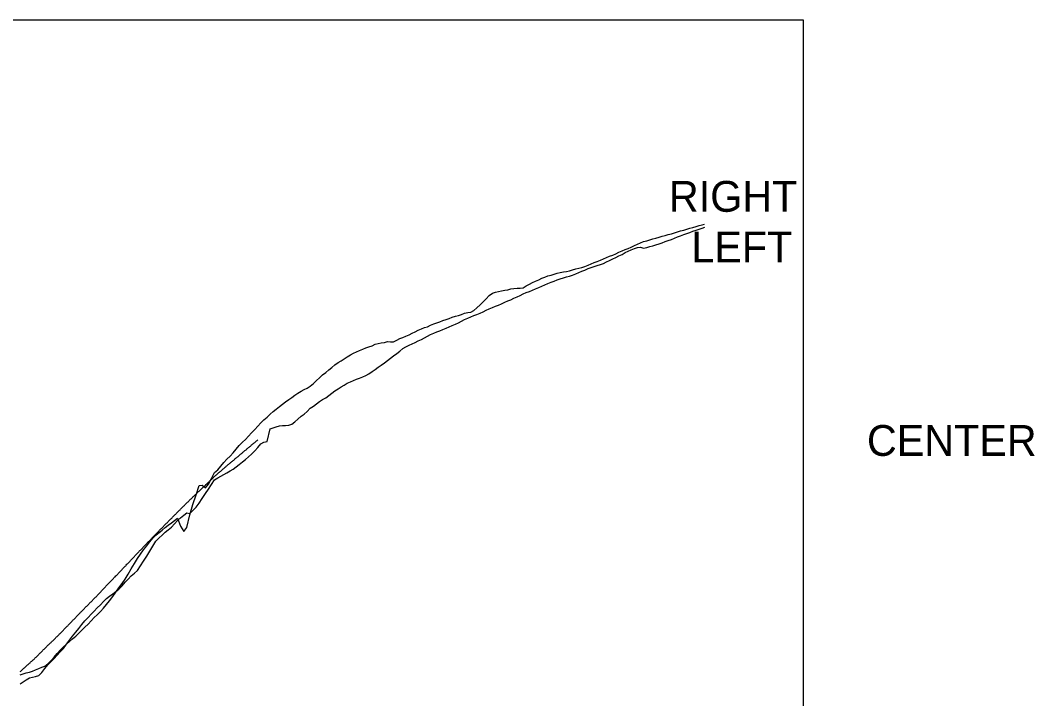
# Model space of a CAD drawing. Extents: x 1733584 to 1737559, y 1214897 to 1219897.
# Drawn here: x 1735916 to 1737559, y 1218220 to 1219320 of the extents above; entities that cross this region are included whole.
import ezdxf

# ---------------------------------------------------------------- set-up
doc = ezdxf.new("R2010")
doc.units = 0
for name, color, linetype in [('RD_DDB_Profile_EX', 7, 'Continuous'), ('RD_Sketch1', 7, 'Continuous'), ('RD_Sketch2', 7, 'Continuous'), ('RD_Sketch8', 7, 'Continuous')]:
    doc.layers.add(name, color=color, linetype=linetype)

msp = doc.modelspace()

# ---------------------------------------------------------------- linework, layer by layer
at = {"layer": 'RD_DDB_Profile_EX'}
for points in [[(1736280.3, 1218623.3), (1736281.3, 1218624.1), (1736282.3, 1218625), (1736283.3, 1218625.8), (1736284.3, 1218626.7), (1736285.3, 1218627.5), (1736286.3, 1218628.3), (1736287.3, 1218629.1), (1736288.3, 1218630), (1736289.3, 1218630.8), (1736290.3, 1218631.7), (1736291.3, 1218632.5), (1736292.3, 1218633.3), (1736293.3, 1218634.2), (1736294.3, 1218635), (1736295.3, 1218635.8), (1736296.3, 1218636.7), (1736297.3, 1218637.5), (1736298.3, 1218638.3), (1736299.3, 1218639.2), (1736300.3, 1218640), (1736300.4, 1218640)], [(1736180.3, 1218532.8), (1736181.3, 1218533.8), (1736182.3, 1218534.8), (1736183.3, 1218535.8), (1736184.3, 1218536.8), (1736185.3, 1218537.8), (1736186.3, 1218538.8), (1736187.3, 1218539.7), (1736188.3, 1218540.7), (1736189.3, 1218541.7), (1736190.3, 1218542.6), (1736191.3, 1218543.6), (1736192.3, 1218544.5), (1736193.3, 1218545.5), (1736194.3, 1218546.5), (1736195.3, 1218547.4), (1736196.3, 1218548.4), (1736197.3, 1218549.4), (1736198.3, 1218550.3), (1736199.3, 1218551.3), (1736200.3, 1218552.2), (1736201.3, 1218553.2), (1736202.3, 1218554.1), (1736203.3, 1218555.1), (1736204.3, 1218556.1), (1736205.3, 1218557), (1736206.3, 1218558), (1736207.3, 1218558.9), (1736208.3, 1218559.9), (1736209.3, 1218560.8), (1736210.3, 1218561.8), (1736211.3, 1218562.7), (1736212.3, 1218563.7), (1736213.3, 1218564.6), (1736214.3, 1218565.6), (1736215.3, 1218566.5), (1736216.3, 1218567.5), (1736217.3, 1218568.4), (1736218.3, 1218569.4), (1736219.3, 1218570.3), (1736220.3, 1218571.3), (1736221.3, 1218572.2), (1736222.3, 1218573.2), (1736223.3, 1218574.1), (1736224.3, 1218575), (1736225.3, 1218576), (1736226.3, 1218576.9), (1736227.3, 1218577.9), (1736228.3, 1218578.8), (1736229.3, 1218579.8), (1736230.3, 1218580.7), (1736231.3, 1218581.6), (1736232.3, 1218582.6), (1736233.3, 1218583.5), (1736234.3, 1218584.4), (1736235.3, 1218585.3), (1736236.3, 1218586.1), (1736237.3, 1218587), (1736238.3, 1218587.8), (1736239.3, 1218588.7), (1736240.3, 1218589.5), (1736241.3, 1218590.4), (1736242.3, 1218591.3), (1736243.3, 1218592.1), (1736244.3, 1218593), (1736245.3, 1218593.8), (1736246.3, 1218594.7), (1736247.3, 1218595.5), (1736248.3, 1218596.4), (1736249.3, 1218597.2), (1736250.3, 1218598.1), (1736251.3, 1218598.9), (1736252.3, 1218599.8), (1736253.3, 1218600.6), (1736254.3, 1218601.5), (1736255.3, 1218602.3), (1736256.3, 1218603.2), (1736257.3, 1218604), (1736258.3, 1218604.9), (1736259.3, 1218605.7), (1736260.3, 1218606.5), (1736261.3, 1218607.3), (1736262.3, 1218608.2), (1736263.3, 1218609), (1736264.3, 1218609.9), (1736265.3, 1218610.7), (1736266.3, 1218611.6), (1736267.3, 1218612.4), (1736268.3, 1218613.2), (1736269.3, 1218614.1), (1736270.3, 1218614.9), (1736271.3, 1218615.8), (1736272.3, 1218616.6), (1736273.3, 1218617.4), (1736274.3, 1218618.3), (1736275.3, 1218619.1), (1736276.3, 1218620), (1736277.3, 1218620.8), (1736278.3, 1218621.6), (1736279.3, 1218622.5), (1736280.3, 1218623.3)], [(1736080.3, 1218429.8), (1736081.3, 1218430.8), (1736082.3, 1218431.9), (1736083.3, 1218432.9), (1736084.3, 1218433.9), (1736085.3, 1218435), (1736086.3, 1218436), (1736087.3, 1218437.1), (1736088.3, 1218438.2), (1736089.3, 1218439.2), (1736090.3, 1218440.3), (1736091.3, 1218441.3), (1736092.3, 1218442.4), (1736093.3, 1218443.5), (1736094.3, 1218444.5), (1736095.3, 1218445.6), (1736096.3, 1218446.6), (1736097.3, 1218447.7), (1736098.3, 1218448.7), (1736099.3, 1218449.8), (1736100.3, 1218450.8), (1736101.3, 1218451.9), (1736102.3, 1218452.9), (1736103.3, 1218454), (1736104.3, 1218455), (1736105.3, 1218456.1), (1736106.3, 1218457.2), (1736107.3, 1218458.2), (1736108.3, 1218459.3), (1736109.3, 1218460.4), (1736110.3, 1218461.4), (1736111.3, 1218462.5), (1736112.3, 1218463.5), (1736113.3, 1218464.6), (1736114.3, 1218465.6), (1736115.3, 1218466.7), (1736116.3, 1218467.7), (1736117.3, 1218468.7), (1736118.3, 1218469.8), (1736119.3, 1218470.8), (1736120.3, 1218471.9), (1736121.3, 1218472.9), (1736122.3, 1218473.9), (1736123.3, 1218475), (1736124.3, 1218476), (1736125.3, 1218477), (1736126.3, 1218478.1), (1736127.3, 1218479.1), (1736128.3, 1218480.1), (1736129.3, 1218481.2), (1736130.3, 1218482.2), (1736131.3, 1218483.2), (1736132.3, 1218484.3), (1736133.3, 1218485.3), (1736134.3, 1218486.4), (1736135.3, 1218487.3), (1736136.3, 1218488.3), (1736137.3, 1218489.4), (1736138.3, 1218490.4), (1736139.3, 1218491.4), (1736140.3, 1218492.5), (1736141.3, 1218493.5), (1736142.3, 1218494.5), (1736143.3, 1218495.5), (1736144.3, 1218496.5), (1736145.3, 1218497.6), (1736146.3, 1218498.6), (1736147.3, 1218499.6), (1736148.3, 1218500.6), (1736149.3, 1218501.6), (1736150.3, 1218502.7), (1736151.3, 1218503.7), (1736152.3, 1218504.7), (1736153.3, 1218505.7), (1736154.3, 1218506.7), (1736155.3, 1218507.7), (1736156.3, 1218508.8), (1736157.3, 1218509.8), (1736158.3, 1218510.8), (1736159.3, 1218511.8), (1736160.3, 1218512.7), (1736161.3, 1218513.7), (1736162.3, 1218514.7), (1736163.3, 1218515.7), (1736164.3, 1218516.7), (1736165.3, 1218517.8), (1736166.3, 1218518.8), (1736167.3, 1218519.8), (1736168.3, 1218520.8), (1736169.3, 1218521.8), (1736170.3, 1218522.8), (1736171.3, 1218523.8), (1736172.3, 1218524.8), (1736173.3, 1218525.8), (1736174.3, 1218526.8), (1736175.3, 1218527.8), (1736176.3, 1218528.8), (1736177.3, 1218529.8), (1736178.3, 1218530.8), (1736179.3, 1218531.8), (1736180.3, 1218532.8)], [(1735980.3, 1218326.3), (1735981.3, 1218327.2), (1735982.3, 1218328.2), (1735983.3, 1218329.2), (1735984.3, 1218330.3), (1735985.3, 1218331.4), (1735986.3, 1218332.4), (1735987.3, 1218333.5), (1735988.3, 1218334.5), (1735989.3, 1218335.6), (1735990.3, 1218336.7), (1735991.3, 1218337.7), (1735992.3, 1218338.7), (1735993.3, 1218339.8), (1735994.3, 1218340.8), (1735995.3, 1218341.8), (1735996.3, 1218342.9), (1735997.3, 1218343.9), (1735998.3, 1218344.9), (1735999.3, 1218345.9), (1736000.3, 1218347), (1736001.3, 1218348), (1736002.3, 1218349), (1736003.3, 1218350), (1736004.3, 1218351.1), (1736005.3, 1218352.1), (1736006.3, 1218353.1), (1736007.3, 1218354.1), (1736008.3, 1218355.2), (1736009.3, 1218356.2), (1736010.3, 1218357.3), (1736011.3, 1218358.3), (1736012.3, 1218359.3), (1736013.3, 1218360.4), (1736014.3, 1218361.4), (1736015.3, 1218362.5), (1736016.3, 1218363.5), (1736017.3, 1218364.5), (1736018.3, 1218365.5), (1736019.3, 1218366.5), (1736020.3, 1218367.5), (1736021.3, 1218368.5), (1736022.3, 1218369.6), (1736023.3, 1218370.6), (1736024.3, 1218371.6), (1736025.3, 1218372.6), (1736026.3, 1218373.6), (1736027.3, 1218374.6), (1736028.3, 1218375.6), (1736029.3, 1218376.6), (1736030.3, 1218377.6), (1736031.3, 1218378.6), (1736032.3, 1218379.6), (1736033.3, 1218380.6), (1736034.3, 1218381.6), (1736035.3, 1218382.6), (1736036.3, 1218383.7), (1736037.3, 1218384.7), (1736038.3, 1218385.7), (1736039.3, 1218386.7), (1736040.3, 1218387.8), (1736041.3, 1218388.8), (1736042.3, 1218389.9), (1736043.3, 1218391), (1736044.3, 1218392), (1736045.3, 1218393.1), (1736046.3, 1218394.2), (1736047.3, 1218395.2), (1736048.3, 1218396.3), (1736049.3, 1218397.4), (1736050.3, 1218398.4), (1736051.3, 1218399.5), (1736052.3, 1218400.5), (1736053.3, 1218401.6), (1736054.3, 1218402.7), (1736055.3, 1218403.7), (1736056.3, 1218404.8), (1736057.3, 1218405.8), (1736058.3, 1218406.9), (1736059.3, 1218408), (1736060.3, 1218409), (1736061.3, 1218410), (1736062.3, 1218411), (1736063.3, 1218412), (1736064.3, 1218413), (1736065.3, 1218414), (1736066.3, 1218415.1), (1736067.3, 1218416.1), (1736068.3, 1218417.2), (1736069.3, 1218418.2), (1736070.3, 1218419.3), (1736071.3, 1218420.3), (1736072.3, 1218421.4), (1736073.3, 1218422.4), (1736074.3, 1218423.5), (1736075.3, 1218424.5), (1736076.3, 1218425.6), (1736077.3, 1218426.6), (1736078.3, 1218427.7), (1736079.3, 1218428.7), (1736080.3, 1218429.8)], [(1735915.3, 1218264.2), (1735916.3, 1218265.1), (1735917.3, 1218266), (1735918.3, 1218266.9), (1735919.3, 1218267.8), (1735920.3, 1218268.7), (1735921.3, 1218269.6), (1735922.3, 1218270.5), (1735923.3, 1218271.4), (1735924.3, 1218272.3), (1735925.3, 1218273.2), (1735926.3, 1218274.1), (1735927.3, 1218275), (1735928.3, 1218275.9), (1735929.3, 1218276.8), (1735930.3, 1218277.7), (1735931.3, 1218278.6), (1735932.3, 1218279.5), (1735933.3, 1218280.4), (1735934.3, 1218281.3), (1735935.3, 1218282.2), (1735936.3, 1218283.1), (1735937.3, 1218284.1), (1735938.3, 1218285), (1735939.3, 1218286), (1735940.3, 1218287), (1735941.3, 1218287.9), (1735942.3, 1218288.9), (1735943.3, 1218289.9), (1735944.3, 1218290.9), (1735945.3, 1218291.9), (1735946.3, 1218292.9), (1735947.3, 1218293.9), (1735948.3, 1218294.9), (1735949.3, 1218295.9), (1735950.3, 1218296.9), (1735951.3, 1218297.9), (1735952.3, 1218298.9), (1735953.3, 1218299.9), (1735954.3, 1218300.9), (1735955.3, 1218301.9), (1735956.3, 1218302.9), (1735957.3, 1218303.9), (1735958.3, 1218304.9), (1735959.3, 1218305.9), (1735960.3, 1218306.9), (1735961.3, 1218307.9), (1735962.3, 1218308.8), (1735963.3, 1218309.7), (1735964.3, 1218310.7), (1735965.3, 1218311.6), (1735966.3, 1218312.5), (1735967.3, 1218313.5), (1735968.3, 1218314.4), (1735969.3, 1218315.4), (1735970.3, 1218316.4), (1735971.3, 1218317.4), (1735972.3, 1218318.4), (1735973.3, 1218319.4), (1735974.3, 1218320.4), (1735975.3, 1218321.3), (1735976.3, 1218322.3), (1735977.3, 1218323.3), (1735978.3, 1218324.3), (1735979.3, 1218325.3), (1735980.3, 1218326.3)]]:
    msp.add_lwpolyline(points, dxfattribs=at)
at = {"layer": 'RD_Sketch1'}
for points in [[(1736880.3, 1218935.8), (1736885.3, 1218938.2), (1736890.3, 1218940.6), (1736895.3, 1218943.9), (1736900.3, 1218946.2), (1736905.3, 1218948.1), (1736910.3, 1218950.1), (1736915.3, 1218951.8), (1736920.3, 1218952.2), (1736925.3, 1218950.6), (1736930.3, 1218951.7), (1736935.3, 1218953.3), (1736940.3, 1218954.8), (1736945.3, 1218956.3), (1736950.3, 1218958), (1736955.3, 1218959.7), (1736960.3, 1218961.4), (1736965.3, 1218963.1), (1736970.3, 1218965), (1736975.3, 1218967), (1736980.3, 1218969), (1736985.3, 1218970.9), (1736990.3, 1218972.9), (1736995.3, 1218974.7), (1737000.3, 1218976.4), (1737005.3, 1218978.1), (1737010.3, 1218979.8), (1737015.3, 1218981.5), (1737020.3, 1218983.3), (1737024.6, 1218984.8)], [(1736380.3, 1218686.2), (1736385.3, 1218691.2), (1736390.3, 1218694.9), (1736395.3, 1218698.5), (1736400.3, 1218702.1), (1736405.3, 1218705.4), (1736410.3, 1218708.2), (1736415.3, 1218711.8), (1736420.3, 1218715.6), (1736425.3, 1218719.4), (1736430.3, 1218722.9), (1736435.3, 1218725.9), (1736440.3, 1218728.9), (1736445.3, 1218731.7), (1736450.3, 1218734.2), (1736455.3, 1218736.2), (1736460.3, 1218738.2), (1736465.3, 1218740.2), (1736470.3, 1218742.3), (1736475.3, 1218744.4), (1736480.3, 1218747.3), (1736485.3, 1218750.6), (1736490.3, 1218754), (1736495.3, 1218757.7), (1736500.3, 1218761.3), (1736505.3, 1218764.9), (1736510.3, 1218768.5), (1736515.3, 1218772.3), (1736520.3, 1218776.2), (1736525.3, 1218780.2), (1736530.3, 1218784), (1736535.3, 1218787.9), (1736540.3, 1218791), (1736545.3, 1218793.3), (1736550.3, 1218795.6), (1736555.3, 1218798), (1736560.3, 1218800.4), (1736565.3, 1218802.9), (1736570.3, 1218805.4), (1736575.3, 1218808), (1736580.3, 1218810.7), (1736585.3, 1218813.1), (1736590.3, 1218814.9), (1736595.3, 1218816.8), (1736600.3, 1218818.8), (1736605.3, 1218821), (1736610.3, 1218823.4), (1736615.3, 1218825.5), (1736620.3, 1218827.6), (1736625.3, 1218829.8), (1736630.3, 1218832.4), (1736635.3, 1218835.1), (1736640.3, 1218837.2), (1736645.3, 1218839.3), (1736650.3, 1218841.6), (1736655.3, 1218843.4), (1736660.3, 1218845.2), (1736665.3, 1218847.7), (1736670.3, 1218850.1), (1736675.3, 1218852.6), (1736680.3, 1218854.6), (1736685.3, 1218856.5), (1736690.3, 1218858.6), (1736695.3, 1218860.8), (1736700.3, 1218863), (1736705.3, 1218865.2), (1736710.3, 1218867.2), (1736715.3, 1218869.5), (1736720.3, 1218871.8), (1736725.3, 1218874.3), (1736730.3, 1218876.7), (1736735.3, 1218878.7), (1736740.3, 1218880.8), (1736745.3, 1218882.9), (1736750.3, 1218884.9), (1736755.3, 1218886.9), (1736760.3, 1218889), (1736765.3, 1218891.2), (1736770.3, 1218893.4), (1736775.3, 1218895.5), (1736780.3, 1218897.4), (1736785.3, 1218899.3), (1736790.3, 1218901.3), (1736795.3, 1218902.9), (1736800.3, 1218904.1), (1736805.3, 1218905.3), (1736810.3, 1218906.9), (1736815.3, 1218909.1), (1736820.3, 1218911.3), (1736825.3, 1218913.4), (1736830.3, 1218915.2), (1736835.3, 1218917.7), (1736840.3, 1218919.5), (1736845.3, 1218921.2), (1736850.3, 1218922.9), (1736855.3, 1218924.3), (1736860.3, 1218925.8), (1736865.3, 1218928.5), (1736870.3, 1218931), (1736875.3, 1218933.4), (1736880.3, 1218935.8)], [(1735915.3, 1218244.3), (1735920.3, 1218247.5), (1735925.3, 1218250.8), (1735930.3, 1218254.2), (1735935.3, 1218255.3), (1735940.3, 1218256.2), (1735945.3, 1218257.7), (1735950.3, 1218263), (1735955.3, 1218269.3), (1735960.3, 1218275.5), (1735965.3, 1218280.6), (1735970.3, 1218285.5), (1735975.3, 1218291), (1735980.3, 1218296.4), (1735985.3, 1218302), (1735990.3, 1218308.7), (1735995.3, 1218315.4), (1736000.3, 1218321.9), (1736005.3, 1218328.3), (1736010.3, 1218334.1), (1736015.3, 1218340.8), (1736020.3, 1218346.6), (1736025.3, 1218351.9), (1736030.3, 1218357.2), (1736035.3, 1218362.5), (1736040.3, 1218367.7), (1736045.3, 1218372.8), (1736050.3, 1218377.8), (1736055.3, 1218382.8), (1736060.3, 1218386.7), (1736065.3, 1218390.5), (1736070.3, 1218394.2), (1736075.3, 1218397.8), (1736080.3, 1218403.4), (1736085.3, 1218409.1), (1736090.3, 1218414.3), (1736095.3, 1218419.4), (1736100.3, 1218423.7), (1736105.3, 1218428.3), (1736110.3, 1218435.7), (1736115.3, 1218443.4), (1736120.3, 1218451.6), (1736125.3, 1218459.6), (1736130.3, 1218467.8), (1736135.3, 1218476), (1736140.3, 1218481), (1736145.3, 1218485.7), (1736150.3, 1218490.1), (1736155.3, 1218494.3), (1736160.3, 1218498.6), (1736165.3, 1218503.7), (1736170.3, 1218509), (1736175.3, 1218513.4), (1736180.3, 1218517.8), (1736185.3, 1218521.8), (1736190.3, 1218520.6), (1736195.3, 1218525.6), (1736200.3, 1218530.9), (1736205.3, 1218537.4), (1736210.3, 1218545), (1736215.3, 1218553), (1736220.3, 1218559.9), (1736225.3, 1218567.5), (1736230.3, 1218575.4), (1736235.3, 1218578.6), (1736240.3, 1218581.1), (1736245.3, 1218583.8), (1736250.3, 1218586.7), (1736255.3, 1218589.6), (1736260.3, 1218592.7), (1736265.3, 1218596.4), (1736270.3, 1218600.2), (1736275.3, 1218604.2), (1736280.3, 1218608.2), (1736285.3, 1218612.4), (1736290.3, 1218616.9), (1736295.3, 1218622.2), (1736300.3, 1218627.8), (1736305.3, 1218633.6), (1736310.3, 1218636.4), (1736315.3, 1218637.6), (1736320.3, 1218657.7), (1736325.3, 1218659.3), (1736330.3, 1218660.9), (1736335.3, 1218662.6), (1736340.3, 1218663.4), (1736345.3, 1218663.1), (1736350.3, 1218664.1), (1736355.3, 1218665.2), (1736360.3, 1218669.1), (1736365.3, 1218673.8), (1736370.3, 1218678.4), (1736375.3, 1218681.5), (1736380.3, 1218686.2)]]:
    msp.add_lwpolyline(points, dxfattribs=at)
at = {"layer": 'RD_Sketch2'}
for points in [[(1736880.3, 1218941.8), (1736885.3, 1218944.1), (1736890.3, 1218946.4), (1736895.3, 1218948.4), (1736900.3, 1218950.4), (1736905.3, 1218952.6), (1736910.3, 1218955), (1736915.3, 1218957.3), (1736920.3, 1218959.5), (1736925.3, 1218961.5), (1736930.3, 1218962.9), (1736935.3, 1218964.3), (1736940.3, 1218965.7), (1736945.3, 1218967.2), (1736950.3, 1218968.6), (1736955.3, 1218970), (1736960.3, 1218971.4), (1736965.3, 1218972.9), (1736970.3, 1218974.3), (1736975.3, 1218975.8), (1736980.3, 1218977.2), (1736985.3, 1218978.7), (1736990.3, 1218980.1), (1736995.3, 1218981.6), (1737000.3, 1218983.1), (1737005.3, 1218984.5), (1737010.3, 1218986), (1737015.3, 1218987.5), (1737020.3, 1218988.9), (1737023.7, 1218989.9)], [(1736380.3, 1218724), (1736385.3, 1218727.1), (1736390.3, 1218731.2), (1736395.3, 1218736), (1736400.3, 1218740.7), (1736405.3, 1218745.2), (1736410.3, 1218749.3), (1736415.3, 1218753.4), (1736420.3, 1218757.5), (1736425.3, 1218761.4), (1736430.3, 1218765.2), (1736435.3, 1218768.4), (1736440.3, 1218771.6), (1736445.3, 1218774.7), (1736450.3, 1218777.6), (1736455.3, 1218780.3), (1736460.3, 1218782.8), (1736465.3, 1218785.1), (1736470.3, 1218787.2), (1736475.3, 1218789.1), (1736480.3, 1218790.9), (1736485.3, 1218792.4), (1736490.3, 1218795.4), (1736495.3, 1218796.4), (1736500.3, 1218797.2), (1736505.3, 1218798.1), (1736510.3, 1218799.3), (1736515.3, 1218799.1), (1736520.3, 1218798.9), (1736525.3, 1218801.7), (1736530.3, 1218804.1), (1736535.3, 1218806.2), (1736540.3, 1218808.2), (1736545.3, 1218810.3), (1736550.3, 1218812.8), (1736555.3, 1218815.4), (1736560.3, 1218817.9), (1736565.3, 1218820.2), (1736570.3, 1218822), (1736575.3, 1218823.4), (1736580.3, 1218825.9), (1736585.3, 1218828.2), (1736590.3, 1218829.9), (1736595.3, 1218831.6), (1736600.3, 1218833.3), (1736605.3, 1218835), (1736610.3, 1218836.8), (1736615.3, 1218838.7), (1736620.3, 1218840.6), (1736625.3, 1218841.9), (1736630.3, 1218843.5), (1736635.3, 1218845.4), (1736640.3, 1218846.3), (1736645.3, 1218847.2), (1736650.3, 1218850), (1736655.3, 1218854), (1736660.3, 1218858.7), (1736665.3, 1218863.9), (1736670.3, 1218868.9), (1736675.3, 1218873.8), (1736680.3, 1218877.9), (1736685.3, 1218879.5), (1736690.3, 1218880.7), (1736695.3, 1218881.8), (1736700.3, 1218882.6), (1736705.3, 1218883.5), (1736710.3, 1218884.7), (1736715.3, 1218885.5), (1736720.3, 1218886), (1736725.3, 1218886.2), (1736730.3, 1218886.7), (1736735.3, 1218889.7), (1736740.3, 1218892.6), (1736745.3, 1218895.1), (1736750.3, 1218897.4), (1736755.3, 1218899.6), (1736760.3, 1218901.9), (1736765.3, 1218904), (1736770.3, 1218905.8), (1736775.3, 1218907.2), (1736780.3, 1218908.7), (1736785.3, 1218910.3), (1736790.3, 1218911.6), (1736795.3, 1218912.2), (1736800.3, 1218912.8), (1736805.3, 1218914.2), (1736810.3, 1218915.8), (1736815.3, 1218917.4), (1736820.3, 1218918.6), (1736825.3, 1218919.4), (1736830.3, 1218921.2), (1736835.3, 1218923.4), (1736840.3, 1218925.4), (1736845.3, 1218927.3), (1736850.3, 1218929.2), (1736855.3, 1218931.4), (1736860.3, 1218933.6), (1736865.3, 1218935.7), (1736870.3, 1218937.7), (1736875.3, 1218939.6), (1736880.3, 1218941.8)], [(1735915.3, 1218259.1), (1735920.3, 1218260.6), (1735925.3, 1218262.1), (1735930.3, 1218263.6), (1735935.3, 1218265), (1735940.3, 1218267.1), (1735945.3, 1218269.1), (1735950.3, 1218271.2), (1735955.3, 1218273.2), (1735960.3, 1218276.9), (1735965.3, 1218282.3), (1735970.3, 1218287.8), (1735975.3, 1218293.4), (1735980.3, 1218299.1), (1735985.3, 1218304.6), (1735990.3, 1218308.7), (1735995.3, 1218312.9), (1736000.3, 1218317.2), (1736005.3, 1218321.7), (1736010.3, 1218326.4), (1736015.3, 1218331.2), (1736020.3, 1218336.2), (1736025.3, 1218341.3), (1736030.3, 1218346.6), (1736035.3, 1218351.9), (1736040.3, 1218356.3), (1736045.3, 1218361.7), (1736050.3, 1218367.2), (1736055.3, 1218372.9), (1736060.3, 1218378.9), (1736065.3, 1218385.9), (1736070.3, 1218393), (1736075.3, 1218400), (1736080.3, 1218407.1), (1736085.3, 1218414.1), (1736090.3, 1218422.5), (1736095.3, 1218430.9), (1736100.3, 1218439.3), (1736105.3, 1218447.8), (1736110.3, 1218454.8), (1736115.3, 1218461.9), (1736120.3, 1218468.1), (1736125.3, 1218474.7), (1736130.3, 1218480.4), (1736135.3, 1218485.5), (1736140.3, 1218489.6), (1736145.3, 1218493.8), (1736150.3, 1218497.8), (1736155.3, 1218501.5), (1736160.3, 1218505.3), (1736165.3, 1218509.2), (1736170.3, 1218512.9), (1736175.3, 1218500), (1736180.3, 1218491.3), (1736185.3, 1218498), (1736190.3, 1218518.3), (1736195.3, 1218535.2), (1736200.3, 1218550.9), (1736205.3, 1218566), (1736210.3, 1218566.5), (1736215.3, 1218562.2), (1736220.3, 1218568.1), (1736225.3, 1218577.6), (1736230.3, 1218587.1), (1736235.3, 1218591.2), (1736240.3, 1218597.4), (1736245.3, 1218603.5), (1736250.3, 1218608.7), (1736255.3, 1218613.3), (1736260.3, 1218618.8), (1736265.3, 1218624.8), (1736270.3, 1218630.7), (1736275.3, 1218636.5), (1736280.3, 1218640.7), (1736285.3, 1218646.2), (1736290.3, 1218651.4), (1736295.3, 1218656.9), (1736300.3, 1218662.2), (1736305.3, 1218667.4), (1736310.3, 1218672.3), (1736315.3, 1218677), (1736320.3, 1218681.6), (1736325.3, 1218685.9), (1736330.3, 1218690), (1736335.3, 1218694), (1736340.3, 1218697.8), (1736345.3, 1218701.6), (1736350.3, 1218705.2), (1736355.3, 1218708.6), (1736360.3, 1218712.4), (1736365.3, 1218715.9), (1736370.3, 1218718.7), (1736375.3, 1218721.4), (1736380.3, 1218724)]]:
    msp.add_lwpolyline(points, dxfattribs=at)
at = {"layer": 'RD_Sketch8'}
msp.add_lwpolyline([(1733584.4, 1217120.3), (1737184.4, 1217120.3), (1737184.4, 1219320.3), (1733584.4, 1219320.3)], close=True, dxfattribs=at)

# ---------------------------------------------------------------- texts
at = {"layer": 'RD_DDB_Profile_EX'}
msp.add_text('CENTER', height=50, dxfattribs=at).set_placement((1737287.1, 1218614))
at = {"layer": 'RD_Sketch1'}
msp.add_text('LEFT', height=50, dxfattribs=at).set_placement((1737002.6, 1218927.8))
at = {"layer": 'RD_Sketch2'}
msp.add_text('RIGHT', height=50, dxfattribs=at).set_placement((1736966.3, 1219009.8))

doc.saveas('drawing.dxf')
